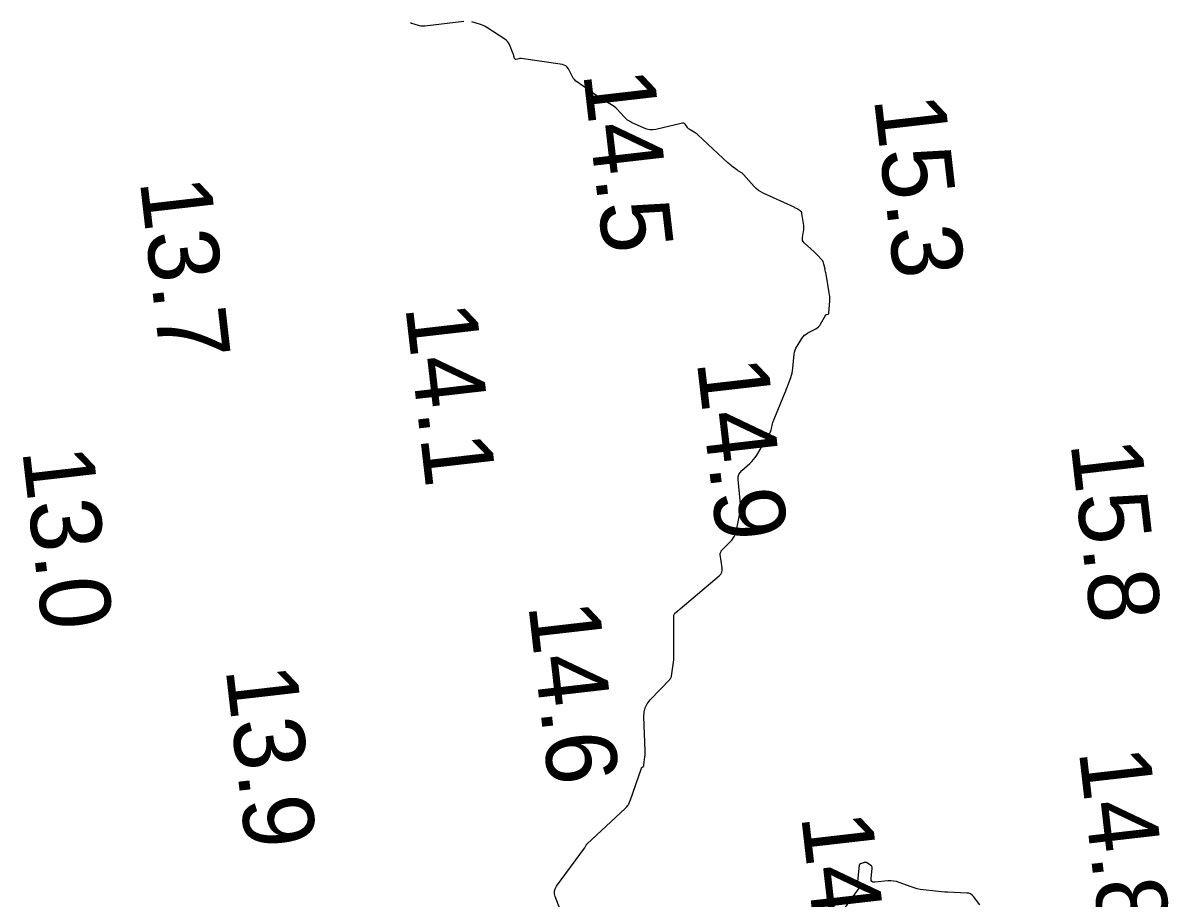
# Model space of a CAD drawing. Extents: x 1023796 to 1112670, y 656573 to 837340.
# Drawn here: x 1109796.4 to 1109877.5, y 681065.6 to 681127.5 of the extents above; entities that cross this region are included whole.
import ezdxf

# ---------------------------------------------------------------- set-up
doc = ezdxf.new("R2010")
doc.units = 0
doc.layers.add('V-CHAN-CONT-15FT', color=7, linetype='Continuous')
doc.layers.add('V-TOPO-SOUN', color=7, linetype='Continuous')

msp = doc.modelspace()

# ---------------------------------------------------------------- linework, layer by layer
at = {"layer": 'V-CHAN-CONT-15FT'}
for points in [[(1109827.603, 681127.584), (1109824.835, 681127.249), (1109824.74, 681127.242), (1109824.645, 681127.245), (1109824.552, 681127.256), (1109824.459, 681127.278), (1109824.089, 681127.381), (1109823.999, 681127.41), (1109823.911, 681127.446), (1109823.826, 681127.489)], [(1109834.456, 681064.635), (1109834.062, 681065.678), (1109834.013, 681065.869), (1109834.013, 681066.053), (1109834.062, 681066.231), (1109834.16, 681066.401), (1109836.14, 681069.107), (1109836.156, 681069.131), (1109836.172, 681069.155), (1109836.186, 681069.18), (1109836.2, 681069.205), (1109836.252, 681069.308), (1109836.266, 681069.332), (1109836.282, 681069.356), (1109836.3, 681069.378), (1109836.32, 681069.398), (1109839.01, 681071.897), (1109839.037, 681071.923), (1109839.063, 681071.949), (1109839.088, 681071.976), (1109839.112, 681072.003), (1109839.217, 681072.125), (1109839.236, 681072.149), (1109839.252, 681072.174), (1109839.266, 681072.2), (1109839.279, 681072.228), (1109839.323, 681072.341), (1109839.334, 681072.369), (1109839.345, 681072.397), (1109839.355, 681072.426), (1109839.365, 681072.454), (1109840.141, 681074.689), (1109840.153, 681074.718), (1109840.168, 681074.745), (1109840.185, 681074.77), (1109840.206, 681074.793), (1109840.295, 681074.881), (1109840.315, 681074.904), (1109840.33, 681074.93), (1109840.34, 681074.958), (1109840.346, 681074.988), (1109840.412, 681075.565), (1109840.422, 681075.671), (1109840.428, 681075.778), (1109840.43, 681075.885), (1109840.428, 681075.992), (1109840.342, 681078.391), (1109840.361, 681078.723), (1109840.442, 681079.032), (1109840.586, 681079.318), (1109840.792, 681079.58), (1109842.198, 681081.063), (1109842.207, 681081.072), (1109842.214, 681081.081), (1109842.222, 681081.091), (1109842.229, 681081.102), (1109842.258, 681081.148), (1109842.268, 681081.165), (1109842.278, 681081.182), (1109842.306, 681081.229), (1109842.307, 681081.231), (1109842.307, 681081.234), (1109842.307, 681081.236), (1109842.306, 681081.238), (1109842.302, 681081.247), (1109842.3, 681081.252), (1109842.3, 681081.256), (1109842.432, 681082.248), (1109842.451, 681082.414), (1109842.464, 681082.581), (1109842.472, 681082.748), (1109842.473, 681082.915), (1109842.455, 681085.517), (1109842.461, 681085.573), (1109842.477, 681085.624), (1109842.505, 681085.67), (1109842.543, 681085.711), (1109842.721, 681085.864), (1109842.766, 681085.902), (1109842.81, 681085.94), (1109842.855, 681085.978), (1109842.899, 681086.016), (1109845.67, 681088.372), (1109845.78, 681088.489), (1109845.851, 681088.62), (1109845.884, 681088.765), (1109845.879, 681088.925), (1109845.744, 681089.867), (1109845.741, 681089.897), (1109845.743, 681089.926), (1109845.749, 681089.955), (1109845.759, 681089.983), (1109845.806, 681090.094), (1109845.819, 681090.121), (1109845.834, 681090.147), (1109845.852, 681090.171), (1109845.872, 681090.193), (1109846.558, 681090.893), (1109846.669, 681091.023), (1109846.757, 681091.164), (1109846.824, 681091.317), (1109846.869, 681091.481), (1109847.108, 681092.664), (1109847.15, 681092.919), (1109847.173, 681093.174), (1109847.177, 681093.43), (1109847.162, 681093.688), (1109847.021, 681095.171), (1109847.023, 681095.354), (1109847.065, 681095.521), (1109847.147, 681095.672), (1109847.27, 681095.807), (1109847.842, 681096.316), (1109847.979, 681096.448), (1109848.105, 681096.59), (1109848.22, 681096.74), (1109848.323, 681096.9), (1109849.251, 681098.463), (1109849.293, 681098.539), (1109849.327, 681098.618), (1109849.356, 681098.698), (1109849.378, 681098.782), (1109849.453, 681099.121), (1109849.474, 681099.205), (1109849.498, 681099.288), (1109849.526, 681099.37), (1109849.558, 681099.45), (1109850.248, 681101.124), (1109850.312, 681101.281), (1109850.375, 681101.438), (1109850.436, 681101.596), (1109850.496, 681101.754), (1109850.733, 681102.389), (1109850.787, 681102.549), (1109850.83, 681102.711), (1109850.862, 681102.876), (1109850.884, 681103.043), (1109850.981, 681104.032), (1109851.005, 681104.185), (1109851.047, 681104.332), (1109851.105, 681104.474), (1109851.181, 681104.61), (1109851.528, 681105.157), (1109851.614, 681105.274), (1109851.712, 681105.377), (1109851.823, 681105.467), (1109851.946, 681105.542), (1109852.507, 681105.837), (1109852.611, 681105.901), (1109852.703, 681105.978), (1109852.782, 681106.068), (1109852.849, 681106.171), (1109853.185, 681106.772), (1109853.201, 681106.796), (1109853.22, 681106.816), (1109853.243, 681106.832), (1109853.268, 681106.844), (1109853.378, 681106.884), (1109853.403, 681106.897), (1109853.421, 681106.914), (1109853.432, 681106.936), (1109853.437, 681106.963), (1109853.492, 681107.8), (1109853.498, 681107.949), (1109853.494, 681108.097), (1109853.482, 681108.245), (1109853.46, 681108.393), (1109853.233, 681109.697), (1109853.216, 681109.788), (1109853.199, 681109.879), (1109853.181, 681109.969), (1109853.161, 681110.06), (1109853.082, 681110.422), (1109853.057, 681110.509), (1109853.021, 681110.591), (1109852.974, 681110.667), (1109852.916, 681110.738), (1109852.659, 681111.013), (1109852.594, 681111.08), (1109852.528, 681111.147), (1109852.461, 681111.212), (1109852.393, 681111.276), (1109851.684, 681111.93), (1109851.617, 681112.007), (1109851.575, 681112.093), (1109851.558, 681112.187), (1109851.565, 681112.289), (1109851.646, 681112.714), (1109851.661, 681112.821), (1109851.668, 681112.927), (1109851.665, 681113.034), (1109851.654, 681113.141), (1109851.526, 681113.994), (1109851.512, 681114.053), (1109851.486, 681114.103), (1109851.449, 681114.147), (1109851.401, 681114.183), (1109851.188, 681114.314), (1109851.135, 681114.346), (1109851.08, 681114.377), (1109851.025, 681114.405), (1109850.968, 681114.432), (1109848.79, 681115.426), (1109848.61, 681115.52), (1109848.443, 681115.63), (1109848.288, 681115.758), (1109848.146, 681115.902), (1109847.394, 681116.748), (1109847.361, 681116.783), (1109847.326, 681116.815), (1109847.288, 681116.844), (1109847.248, 681116.871), (1109847.084, 681116.972), (1109847.043, 681116.997), (1109847.003, 681117.024), (1109846.964, 681117.051), (1109846.925, 681117.08), (1109846.558, 681117.354), (1109846.485, 681117.41), (1109846.413, 681117.468), (1109846.343, 681117.528), (1109846.275, 681117.59), (1109844.165, 681119.564), (1109844.106, 681119.616), (1109844.044, 681119.664), (1109843.98, 681119.709), (1109843.912, 681119.75), (1109843.615, 681119.918), (1109843.56, 681119.953), (1109843.51, 681119.994), (1109843.464, 681120.039), (1109843.423, 681120.09), (1109843.269, 681120.305), (1109843.228, 681120.35), (1109843.18, 681120.378), (1109843.125, 681120.389), (1109843.064, 681120.382), (1109841.183, 681119.943), (1109840.971, 681119.91), (1109840.762, 681119.914), (1109840.558, 681119.953), (1109840.357, 681120.028), (1109839.461, 681120.444), (1109839.316, 681120.52), (1109839.181, 681120.609), (1109839.056, 681120.712), (1109838.94, 681120.828), (1109838.447, 681121.372), (1109838.358, 681121.463), (1109838.263, 681121.545), (1109838.161, 681121.62), (1109838.053, 681121.686), (1109837.608, 681121.934), (1109837.497, 681121.997), (1109837.388, 681122.063), (1109837.281, 681122.132), (1109837.176, 681122.204), (1109835.639, 681123.275), (1109835.526, 681123.365), (1109835.426, 681123.466), (1109835.339, 681123.58), (1109835.265, 681123.704), (1109834.998, 681124.227), (1109834.922, 681124.344), (1109834.825, 681124.434), (1109834.71, 681124.496), (1109834.574, 681124.531), (1109831.67, 681124.959), (1109831.625, 681124.963), (1109831.579, 681124.963), (1109831.534, 681124.958), (1109831.489, 681124.948), (1109831.304, 681124.899), (1109831.266, 681124.895), (1109831.236, 681124.903), (1109831.213, 681124.925), (1109831.197, 681124.96), (1109831.149, 681125.126), (1109831.136, 681125.167), (1109831.123, 681125.208), (1109831.108, 681125.249), (1109831.092, 681125.289), (1109830.823, 681125.941), (1109830.765, 681126.057), (1109830.692, 681126.16), (1109830.605, 681126.251), (1109830.502, 681126.329), (1109829.229, 681127.16), (1109829.107, 681127.233), (1109828.981, 681127.296), (1109828.85, 681127.349), (1109828.714, 681127.392), (1109828.163, 681127.543)], [(1109864.119, 681065.078), (1109863.658, 681065.682), (1109863.564, 681065.782), (1109863.456, 681065.856), (1109863.334, 681065.902), (1109863.197, 681065.921), (1109861.847, 681065.975), (1109861.628, 681065.986), (1109861.409, 681066.001), (1109861.191, 681066.021), (1109860.973, 681066.044), (1109860.101, 681066.147), (1109859.885, 681066.179), (1109859.672, 681066.224), (1109859.461, 681066.282), (1109859.254, 681066.353), (1109858.402, 681066.672), (1109858.209, 681066.733), (1109858.012, 681066.77), (1109857.813, 681066.785), (1109857.61, 681066.776), (1109856.674, 681066.684), (1109856.55, 681066.689), (1109856.465, 681066.734), (1109856.421, 681066.819), (1109856.417, 681066.944), (1109856.498, 681067.679), (1109856.497, 681067.741), (1109856.481, 681067.795), (1109856.449, 681067.842), (1109856.401, 681067.881), (1109856.104, 681068.072), (1109856.086, 681068.082), (1109856.067, 681068.088), (1109856.047, 681068.09), (1109856.027, 681068.089), (1109855.944, 681068.077), (1109855.923, 681068.074), (1109855.902, 681068.07), (1109855.882, 681068.064), (1109855.862, 681068.058), (1109855.67, 681067.994), (1109855.636, 681067.978), (1109855.61, 681067.955), (1109855.593, 681067.925), (1109855.584, 681067.888), (1109855.457, 681066.736), (1109855.455, 681066.693), (1109855.459, 681066.651), (1109855.47, 681066.61), (1109855.486, 681066.57), (1109855.564, 681066.412), (1109855.577, 681066.373), (1109855.58, 681066.335), (1109855.571, 681066.298), (1109855.551, 681066.262), (1109853.242, 681063.053)]]:
    msp.add_lwpolyline(points, dxfattribs=at)

# ---------------------------------------------------------------- texts
at = {"layer": 'V-TOPO-SOUN'}
for s, p in [('14.5 ', (1109836.04, 681123.93)), ('15.3 ', (1109856.611, 681122.153)), ('13.7 ', (1109804.671, 681116.313)), ('14.1 ', (1109823.452, 681107.423)), ('14.9 ', (1109844.081, 681103.543)), ('15.8 ', (1109870.521, 681097.773)), ('13.0 ', (1109796.348, 681097.251)), ('14.6 ', (1109832.158, 681086.31)), ('13.9 ', (1109810.741, 681081.793)), ('14.8 ', (1109871.111, 681075.983)), ('14.9 ', (1109851.461, 681071.393))]:
    msp.add_text(s, height=5, rotation=276.55942, dxfattribs=at).set_placement(p)

doc.saveas('drawing.dxf')
